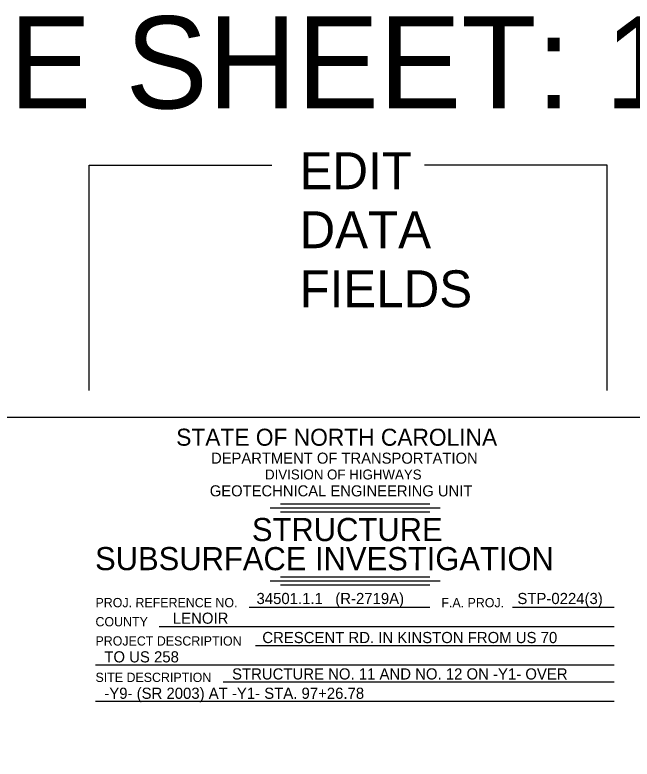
# Model space of a CAD drawing. Extents: x 278710 to 279187, y 171464 to 171625.
# Drawn here: x 278796.7 to 278863.6, y 171543.9 to 171624.6 of the extents above; entities that cross this region are included whole.
import ezdxf

# ---------------------------------------------------------------- set-up
doc = ezdxf.new("R2010")
doc.units = 0
doc.layers.add('Geotech Sheets and Borders Cell', color=7, linetype='Continuous')
doc.layers.add('Prop Strc Sect_ Misc - User Comment (Tx - small)', color=7, linetype='Continuous')

msp = doc.modelspace()

# ---------------------------------------------------------------- linework, layer by layer
at = {"layer": 'Geotech Sheets and Borders Cell'}
for p, q in [((278825.512, 171571.572), (278841.686, 171571.572)), ((278824.376, 171571.14), (278842.821, 171571.14)), ((278825.512, 171570.709), (278841.686, 171570.709)), ((278824.376, 171563.208), (278842.821, 171563.208)), ((278825.512, 171563.64), (278841.686, 171563.64)), ((278825.512, 171562.777), (278841.686, 171562.777)), ((278822.088, 171560.345), (278841.704, 171560.345)), ((278850.671, 171560.339), (278861.686, 171560.339)), ((278812.347, 171558.272), (278861.686, 171558.272)), ((278822.769, 171556.186), (278861.686, 171556.186)), ((278805.427, 171554.104), (278861.686, 171554.104)), ((278819.279, 171552.237), (278861.687, 171552.237)), ((278805.428, 171550.155), (278861.687, 171550.155))]:
    msp.add_line(p, q, dxfattribs=at)
for points in [[(278804.734, 171583.842), (278804.734, 171608.273), (278824.55, 171608.273)], [(278860.915, 171583.842), (278860.915, 171608.273), (278841.099, 171608.273)]]:
    msp.add_lwpolyline(points, dxfattribs=at)
msp.add_lwpolyline([(278756.087, 171580.949), (278907.338, 171580.949), (278907.338, 171476.081), (278756.087, 171476.081)], close=True, dxfattribs=at)

# ---------------------------------------------------------------- texts
for s, height, p in [('EDIT', 4, (278827.56, 171605.683)), ('DATA', 4, (278827.56, 171599.283)), ('FIELDS', 4, (278827.56, 171592.883)), ('34501.1.1   (R-2719A)', 1.2096, (278822.894, 171560.69)), ('STP-0224(3)', 1.2096, (278851.195, 171560.69)), ('LENOIR', 1.2096, (278813.819, 171558.552)), ('CRESCENT RD. IN KINSTON FROM US 70 ', 1.2096, (278823.521, 171556.456)), ('TO US 258', 1.2096, (278806.382, 171554.36)), ('STRUCTURE NO. 11 AND NO. 12 ON -Y1- OVER  ', 1.2096, (278820.239, 171552.507)), ('-Y9- (SR 2003) AT -Y1- STA. 97+26.78', 1.2096, (278806.383, 171550.411))]:
    msp.add_text(s, height=height, dxfattribs=at).set_placement(p)
for s, height, p in [('STATE OF NORTH CAROLINA', 1.84505, (278814.181, 171577.863)), ('DEPARTMENT OF TRANSPORTATION', 1.19808, (278817.959, 171575.918)), ('DIVISION OF HIGHWAYS', 1.07827, (278823.816, 171574.203)), ('GEOTECHNICAL ENGINEERING UNIT', 1.19808, (278817.824, 171572.371)), ('STRUCTURE', 2.5088, (278822.392, 171567.52)), ('SUBSURFACE INVESTIGATION', 2.5088, (278805.379, 171564.365)), ('PROJ. REFERENCE NO.', 1.00637, (278805.426, 171560.346)), ('F.A. PROJ.', 1.0064, (278842.947, 171560.341)), ('COUNTY', 1.0064, (278805.425, 171558.272)), ('PROJECT DESCRIPTION', 1.00637, (278805.424, 171556.188)), ('SITE DESCRIPTION', 1.00637, (278805.425, 171552.239))]:
    msp.add_text(s, height=height, rotation=359.98728, dxfattribs=at).set_placement(p)
at = {"layer": 'Prop Strc Sect_ Misc - User Comment (Tx - small)'}
msp.add_text('TITLE SHEET: 11" x 17"', height=10, dxfattribs=at).set_placement((278768.566, 171614.437))

doc.saveas('drawing.dxf')
